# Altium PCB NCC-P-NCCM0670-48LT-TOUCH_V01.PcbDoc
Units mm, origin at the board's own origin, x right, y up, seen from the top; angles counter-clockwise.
Board outline 105 x 62 mm, 2 copper layers (Top Layer, Bottom Layer); 70 components, 72 nets, 253 pads, 227 vias.
Unrouted connection lines stored in the file: 181.
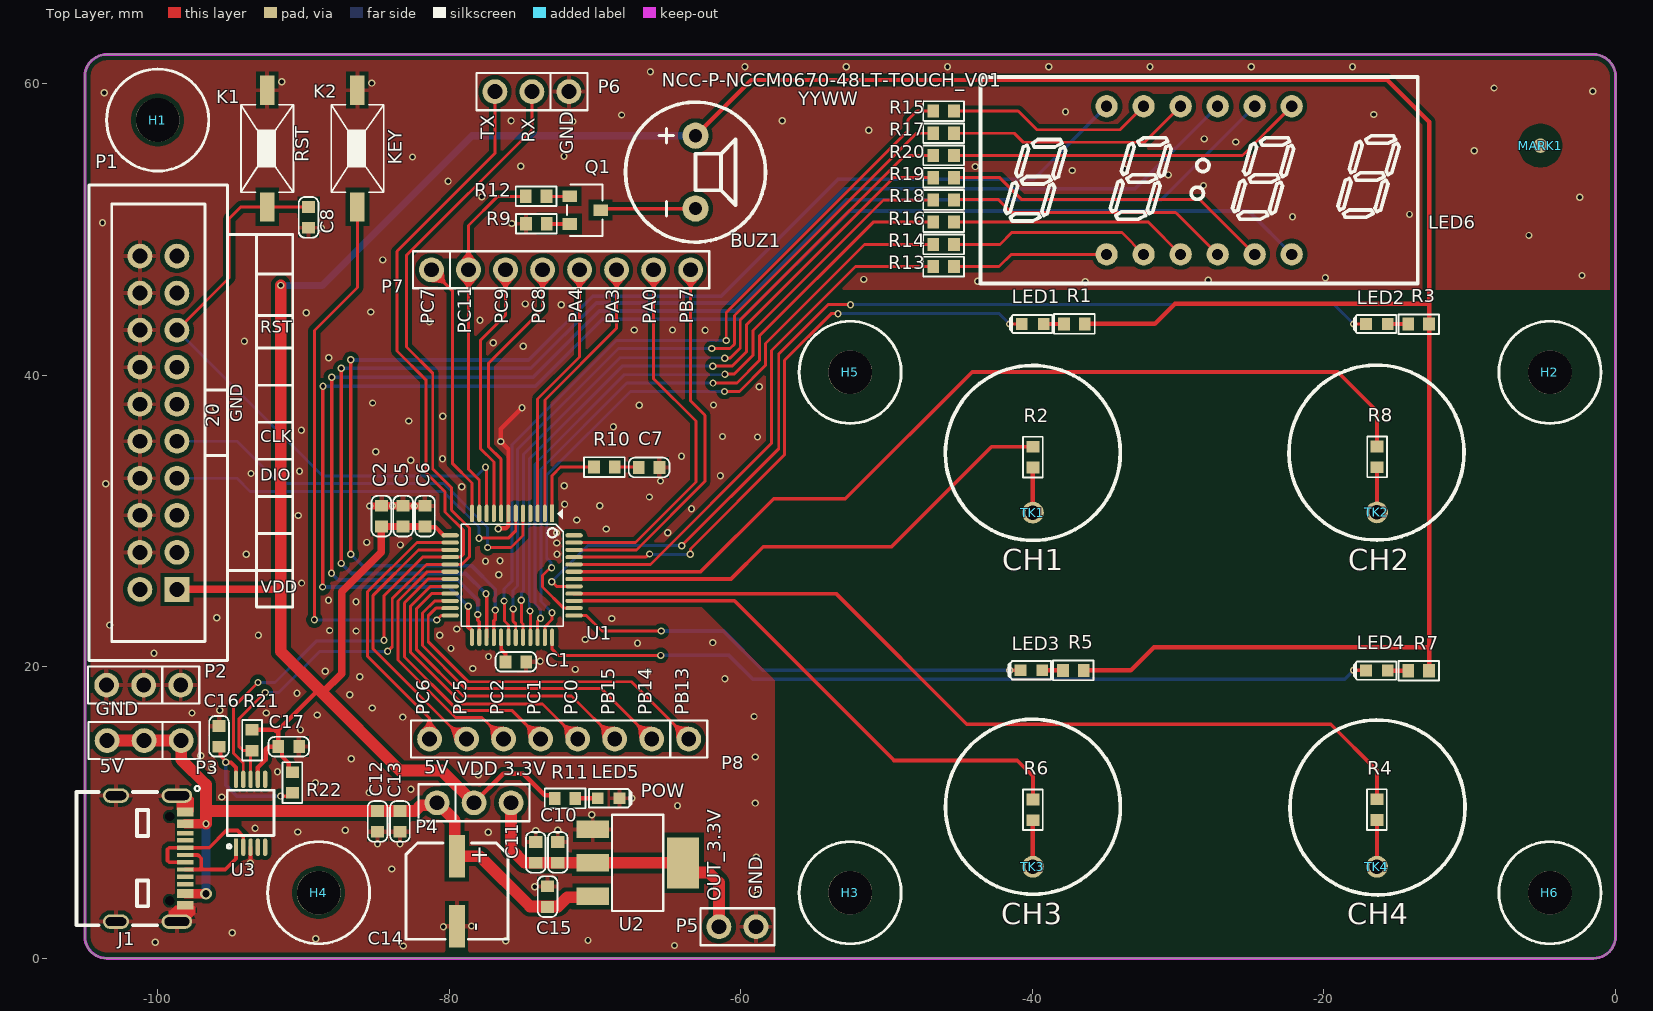
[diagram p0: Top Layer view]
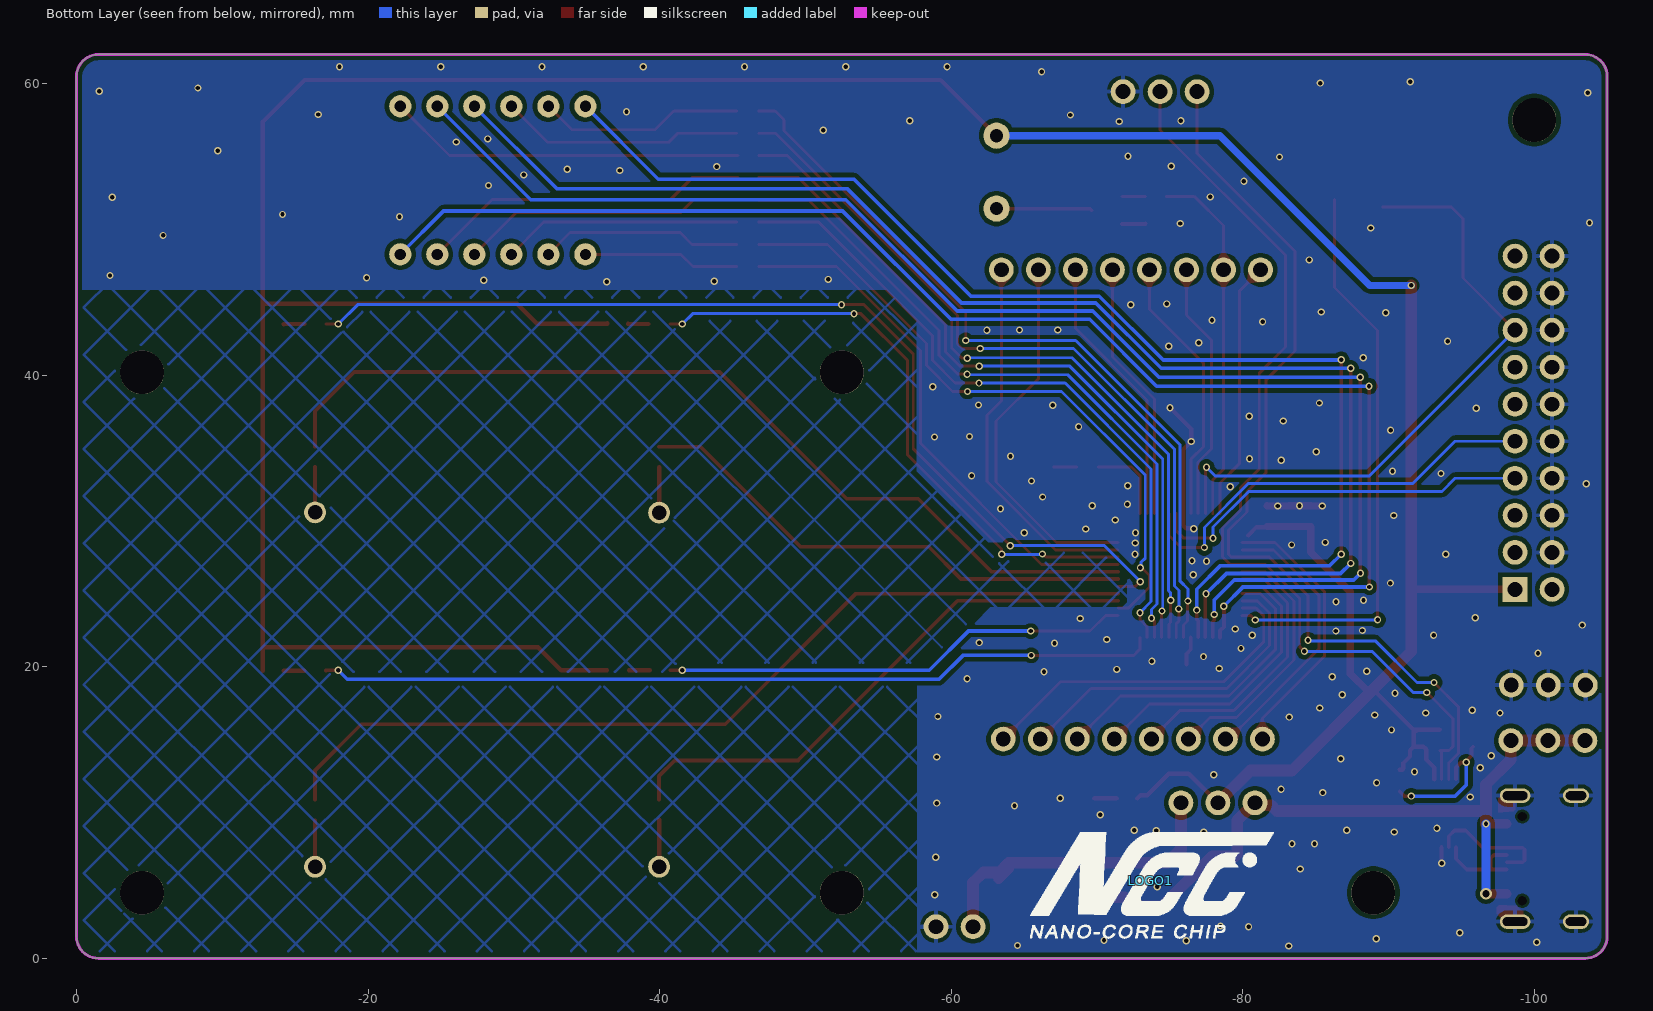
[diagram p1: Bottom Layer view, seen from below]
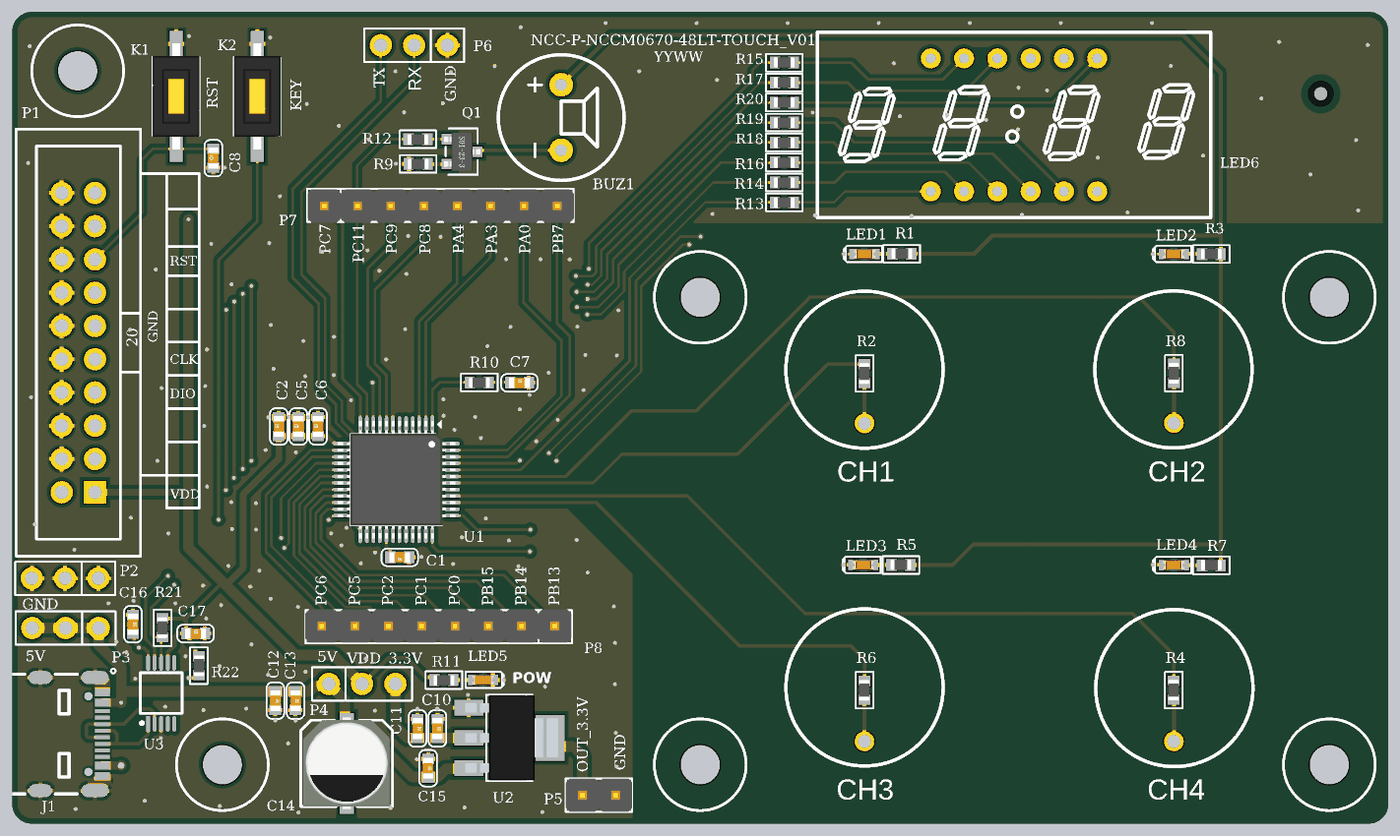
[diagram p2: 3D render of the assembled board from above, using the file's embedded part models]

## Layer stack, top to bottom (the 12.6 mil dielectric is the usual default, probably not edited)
Top Solder: solder mask 0.0102, Solder Resist, Dk 3.5
Top Layer: signal copper 0.0356
Dielectric 1: dielectric 0.32, FR-4, Dk 4.8
Bottom Layer: signal copper 0.0356
Bottom Solder: solder mask 0.0102, Solder Resist, Dk 3.5

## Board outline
-105,1.5 ccw(c-103.5,1.5) -103.5,0 -1.5,0 ccw(c-1.5,1.5) 0,1.5 0,60.5 ccw(c-1.5,60.5) -1.5,62 -103.5,62 ccw(c-103.5,60.5) -105,60.5

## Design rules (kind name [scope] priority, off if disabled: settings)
Clearance Clearance_2 [InComponent('J1')] p1: gap=0.15 ignorepadtopadclearanceinfootprint=FALSE
Clearance Clearance_1 [IsVia vs IsVia] p2: gap=0.3 ignorepadtopadclearanceinfootprint=FALSE
Clearance touch [InNet('KEY0') or InNet('KEY1') or InNet('KEY2') or InNet('KEY3') or InNet('KEY4') or InNet('KEY5') or InNet('NetKEY0_1') or InNet('NetKEY1_1') or InNet('NetKEY2_1') or InNet('NetKEY3_1') or InNet('NetKEY4_1') or InNet('NetKEY5_1') vs InPolygon] p3: gap=0.762 ignorepadtopadclearanceinfootprint=FALSE
Clearance polygon [InPolygon] p4: gap=0.3 ignorepadtopadclearanceinfootprint=FALSE
Clearance keepout [OnLayer('Keep-Out Layer')] p5: gap=0.35 ignorepadtopadclearanceinfootprint=FALSE
Clearance [All] p6: gap=0.2 ignorepadtopadclearanceinfootprint=FALSE
ComponentClearance [All] p1: gap=0 collisioncheckmode=3 verticalgap=0 showdistances=FALSE
HoleToHoleClearance [All] p1: gap=0 allowstackedmicrovias=TRUE
MinimumSolderMaskSliver [All] p1: minsoldermaskwidth=0
PolygonConnect isvia [isvia] p1: connectstyle=Direct reliefconductorwidth=0.254 reliefentries=4 polygonreliefangle="90 Angle" airgapwidth=0.254
PolygonConnect [All] p2: connectstyle=Relief reliefconductorwidth=0.3 reliefentries=4 polygonreliefangle="90 Angle" airgapwidth=0.25
RoutingVias [All] p1: holewidth=0.3 width=0.5 viastyle="Through Hole" minholewidth=0.25 minwidth=0.45 maxholewidth=0.5 maxwidth=0.8
SilkToSilkClearance [All] p1: silktosilkclearance=0
SilkToSolderMaskClearance [IsPad] p1: minsilkscreentomaskgap=0 clearancetoexposedcopper=TRUE
SolderMaskExpansion [All] p1: expansion=0.102 istentingtop=FALSE
Width [All] p1: maxlimit=5 minlimit=0.2 preferedwidth=0.3
25 further rules are at their usual default settings.

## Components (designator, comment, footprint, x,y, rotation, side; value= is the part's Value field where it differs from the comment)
BUZ1 "BUZZER-SMD/DIP-2P" BUZZER-D9P5-2P -63.11,53.93 r270 top
C1 "4.7nF" 0603C_0.6D -75.43,20.34 r180 top
C2 "10uF" 0603C_0.6D -84.657,30.334 r90 top
C5 "1uF" 0603C_0.6D -83.167,30.334 r90 top
C6 "0.1uF" 0603C_0.6D -81.667,30.334 r90 top
C7 "10pF" 0603C_0.6D -66.294,33.673 r0 top
C8 "0.1uF" 0603C_0.6D -89.65,50.828 r90 top
C10 "0.1uF" 0603C_0.6D -72.556,7.269 r270 top
C11 "10uF" 0603C_0.6D -74.066,7.269 r270 top
C12 "0.1uF" 0603C_0.6D -84.92,9.39 r270 top
C13 "10uF" 0603C_0.6D -83.38,9.39 r270 top
C14 "47uF" CS-L6.6W6.6 -79.48,4.61 r90 top
C15 "10uF" 0603C_0.6D -73.26,4.232 r270 top
C16 "0.1uF" 0603C_0.6D -95.79,15.23 r270 top
C17 "0.1uF" 0603C_0.6D -91.01,14.52 r0 top
H1 "HOLE" Toolinghole-3 -100,57.5 r0 top
H2 "HOLE" Toolinghole-3 -4.5,40.2 r0 top
H3 "HOLE" Toolinghole-3 -52.5,4.5 r180 top
H4 "HOLE" Toolinghole-3 -88.96,4.5 r0 top
H5 "HOLE" Toolinghole-3 -52.5,40.2 r0 top
H6 "HOLE" Toolinghole-3 -4.5,4.5 r180 top
J1 "TYPE-C_12P" TYPE-C-12 -100.49,6.84 r270 top locked
K1 "BUTTON-2" SW-6X3X2.5-2P-S -92.49,55.55 r90 top
K2 "BUTTON-2" SW-6X3X2.5-2P-S -86.3,55.55 r90 top
LED1 "DIODE-LED" D0603 -39.97,43.51 r0 top
LED2 "DIODE-LED" D0603 -16.37,43.51 r0 top locked
LED3 "DIODE-LED" D0603 -40.062,19.763 r0 top
LED4 "DIODE-LED" D0603 -16.37,19.74 r0 top locked
LED5 "DIODE-LED" D0603 -69.07,10.98 r180 top
LED6 "FJ3462AH" LED-SEG-TH_12P-L30.0-W14.0-P2.54-S10.16-BL_FJ3462XH -28.56,53.37 r0 top locked
LOGO1 "LOGO" LOGO-NCC -73.68,5.32 r180 bottom
MARK1 "MARK" MARK-Single -5.15,55.75 r0 top
P1 "HDR 20-D-M" "DC3 2.54_20" -99.95,36.74 r90 top locked
P2 "HDR 3-M" "SIP 2.54_3_S" -98.42,18.74 r270 top
P3 "HDR 3-M" "SIP 2.54_3_S" -98.39,14.94 r270 top
P4 "HDR 3-M" "SIP 2.54_3_S" -80.84,10.67 r90 top
P5 "HDR 2-M" "SIP 2.54_2_S" -61.5,2.17 r90 top
P6 "HDR 3-M" "SIP 2.54_3_S" -71.79,59.45 r270 top
P7 "HDR 8-M" "SIP 2.54_8_S" -81.22,47.23 r90 top
P8 "HDR 8-M" "SIP 2.54_8_S" -63.57,15.04 r270 top
Q1 "NPN" SOT-23-3A -70.671,51.323 r180 top
R1 "510R" 0603R_0.6D -37.12,43.52 r180 top
R2 "510R" 0603R_0.6D -39.96,34.379 r270 top
R3 "510R" 0603R_0.6D -13.5,43.5 r180 top
R4 "510R" 0603R_0.6D -16.371,10.2 r270 top
R5 "510R" 0603R_0.6D -37.192,19.753 r180 top
R6 "510R" 0603R_0.6D -39.961,10.188 r270 top
R7 "510R" 0603R_0.6D -13.5,19.73 r180 top
R8 "510R" 0603R_0.6D -16.36,34.4 r270 top
R9 "330R" 0603R_0.6D -74.021,50.393 r0 top
R10 "510R" 0603R_0.6D -69.354,33.703 r0 top
R11 "2K" 0603R_0.6D -72.058,10.967 r0 top
R12 "1K" 0603R_0.6D -74.042,52.273 r0 top
R13 "100R" 0603R_0.6D -46.09,47.449 r0 top
R14 "100R" 0603R_0.6D -46.09,48.974 r0 top
R15 "100R" 0603R_0.6D -46.09,58.123 r180 top
R16 "100R" 0603R_0.6D -46.09,50.499 r0 top
R17 "100R" 0603R_0.6D -46.09,56.598 r180 top
R18 "100R" 0603R_0.6D -46.09,52.024 r0 top
R19 "100R" 0603R_0.6D -46.09,53.548 r0 top
R20 "100R" 0603R_0.6D -46.09,55.073 r180 top
R21 "2K" 0603R_0.6D -93.52,14.962 r270 top
R22 "0R" 0603R_0.6D -90.76,12.06 r90 top
TK1 "HDR 1-M" TOUCH_PAD_1.5/1.0 -39.964,30.57 r180 top locked
TK2 "HDR 1-M" TOUCH_PAD_1.5/1.0 -16.364,30.591 r180 top locked
TK3 "HDR 1-M" TOUCH_PAD_1.5/1.0 -39.964,6.281 r180 top locked
TK4 "HDR 1-M" TOUCH_PAD_1.5/1.0 -16.364,6.281 r180 top locked
U1 "ATM0F3170C-LA7_simple" LQFP48(0.5)-7X7 -75.69,26.27 r270 top locked
U2 "AMS1117-3.3V" SOT-223-4 -67.056,6.549 r180 top
U3 "CH340E" MSOP10(0.5)-3x3 -93.63,9.95 r90 top

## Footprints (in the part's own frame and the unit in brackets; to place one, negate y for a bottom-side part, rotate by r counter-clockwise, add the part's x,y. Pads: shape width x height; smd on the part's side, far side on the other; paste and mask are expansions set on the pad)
0603C_0.6D [mm]
  rect 0.8x0.9 smd mask+0.076: 1(-0.712,0) 2(0.712,0)
  silkscreen extent -1.4,-0.68 1.4,0.67, body extent -0.8,-0.4 0.8,0.4, height 0.3
0603R_0.6D [mm]
  rect 0.8x0.9 smd: 1(-0.712,0) 2(0.712,0)
  silkscreen extent -1.4,-0.67 1.4,0.67, body extent -0.8,-0.42 0.8,0.38, height 0.38
BUZZER-D9P5-2P [mm]
  round 1.8 hole 0.9: 1(-2.5,0) 2(2.5,0)
  silkscreen extent -4.8,-4.8 4.8,4.8
CS-L6.6W6.6 [mm]
  rect 2.9x1.1 smd: 1(2.4,0) 2(-2.4,0)
  silkscreen extent -3.3,-3.5 3.3,3.5, body extent -3.5,-3.3 3.5,3.3, height 5.41
D0603 [mm]
  rect 0.8x0.8 smd: A(0.75,0) K(-0.75,0)
  silkscreen extent -1.59,-0.63 1.33,0.63, body extent -0.81,-0.4 0.81,0.4, height 0.6
"DC3 2.54_20" [mm]
  rect 1.7x1.7 hole 1.02: 1(-11.43,-1.27)
  round 1.7 hole 1.02: 2(-11.43,1.27) 3(-8.89,-1.27) 4(-8.89,1.27) 5(-6.35,-1.27) 6(-6.35,1.27) 7(-3.81,-1.27) 8(-3.81,1.27) 9(-1.27,-1.27) 10(-1.27,1.27) 11(1.27,-1.27) 12(1.27,1.27) 13(3.81,-1.27) 14(3.81,1.27) 15(6.35,-1.27) 16(6.35,1.27) 17(8.89,-1.27) 18(8.89,1.27) 19(11.43,-1.27) 20(11.43,1.27)
  silkscreen extent -16.31,-4.75 16.31,4.75
LED-SEG-TH_12P-L30.0-W14.0-P2.54-S10.16-BL_FJ3462XH [mil]
  round 60 hole 30: 1(-250,-200) 2(-150,-200) 3(-50,-200) 4(50,-200) 5(150,-200) 6(250,-200) 7(250,200) 8(150,200) 9(50,200) 10(-50,200) 11(-150,200) 12(-250,200)
  silkscreen extent -591,-279 591,279
LOGO-NCC [mm]
  silkscreen extent -8.25,-3.96 8.46,3.3
LQFP48(0.5)-7X7 [mm]
  rect 1.2x0.28 smd mask+0.051: 1(-4.25,2.75)
  oval 1.2x0.28 smd mask+0.051: 2(-4.25,2.25) 3(-4.25,1.75) 4(-4.25,1.25) 5(-4.25,0.75) 6(-4.25,0.25) 7(-4.25,-0.25) 8(-4.25,-0.75) 9(-4.25,-1.25) 10(-4.25,-1.75) 11(-4.25,-2.25) 12(-4.25,-2.75) 25(4.25,-2.75) 26(4.25,-2.25) 27(4.25,-1.75) 28(4.25,-1.25) 29(4.25,-0.75) 30(4.25,-0.25) 31(4.25,0.25) 32(4.25,0.75) 33(4.25,1.25) 34(4.25,1.75) 35(4.25,2.25) 36(4.25,2.75)
  oval 0.28x1.2 smd mask+0.051: 13(-2.75,-4.25) 14(-2.25,-4.25) 15(-1.75,-4.25) 16(-1.25,-4.25) 17(-0.75,-4.25) 18(-0.25,-4.25) 19(0.25,-4.25) 20(0.75,-4.25) 21(1.25,-4.25) 22(1.75,-4.25) 23(2.25,-4.25) 24(2.75,-4.25) 37(2.75,4.25) 38(2.25,4.25) 39(1.75,4.25) 40(1.25,4.25) 41(0.75,4.25) 42(0.25,4.25) 43(-0.25,4.25) 44(-0.75,4.25) 45(-1.25,4.25) 46(-1.75,4.25) 47(-2.25,4.25) 48(-2.75,4.25)
  round 0.3 on Mech15 mask+0.3: ""(-4.25,2.75)
  silkscreen extent -4.58,-3.5 3.5,3.5, body extent -4.5,-4.49 4.5,4.51, height 1.56
MARK-Single [mm]
  round 1 smd mask+0.5: 1(0,0)
  Top Layer pour cut-out: -1.5,0 -1.386,-0.574 -1.061,-1.061 -0.574,-1.386 0,-1.5 0,-1.5 0.574,-1.386 1.061,-1.061 1.386,-0.574 1.5,0 1.5,0 1.386,0.574 1.061,1.061 0.574,1.386 0,1.5 0,1.5 -0.574,1.386 -1.061,1.061 -1.386,0.574 -1.5,0
MSOP10(0.5)-3x3 [mm]
  rect 1.2x0.3 smd mask+0.05: 1(-2.325,1)
  oval 1.2x0.3 smd mask+0.05: 2(-2.325,0.5) 3(-2.325,0) 4(-2.325,-0.5) 5(-2.325,-1) 6(2.325,-1) 7(2.325,-0.5) 8(2.325,0) 9(2.325,0.5) 10(2.325,1)
  rect 0.5x0.25 on Mech1 mask+0.051: ""(-2.25,-1) ""(-2.25,-0.5) ""(-2.25,0) ""(-2.25,0.5) ""(-2.25,1)
  silkscreen extent -2.4,-1.6 1.58,1.6, body extent -1.5,-1.5 1.5,1.5, height 1.09
"SIP 2.54_2_S" [mm]
  round 1.7 hole 1.02: 1(0,0) 2(0,-2.54)
  silkscreen extent -1.27,-3.81 1.27,1.27, body extent -1.27,-3.81 1.27,1.27, height 10.3
"SIP 2.54_3_S" [mm]
  round 1.7 hole 1.02: 1(0,0) 2(0,-2.54) 3(0,-5.08)
  silkscreen extent -1.27,-6.35 1.27,1.27
"SIP 2.54_8_S" [mm]
  round 1.7 hole 1.02: 1(0,0) 2(0,-2.54) 3(0,-5.08) 4(0,-7.62) 5(0,-10.16) 6(0,-12.7) 7(0,-15.24) 8(0,-17.78)
  silkscreen extent -1.27,-19.05 1.27,1.27, body extent -1.32,-19.08 1.22,1.24, height 0.7
SOT-23-3A [mm]
  rect 1x0.8 smd: B(1.05,-0.95) C(-1.05,0) E(1.05,0.95)
  rect 0.55x0.5 on Mech1: ""(-1.025,0) ""(1.025,0.95) ""(1.025,-0.95)
  silkscreen extent -1.19,-1.77 1.25,1.77, body extent -1.41,-1.45 1.41,1.45, height 1.22
SOT-223-4 [mm]
  rect 2.2x1.2 smd: 1(3.1,-2.3) 2(3.1,0) 3(3.1,2.3)
  rect 2.2x3.5 smd: 2(-3.1,0)
  silkscreen extent -1.74,-3.3 1.77,3.3, body extent -3.72,-3.25 3.37,3.25, height 1.65
SW-6X3X2.5-2P-S [mm]
  rect 2x1 smd: 1(-4,0) 2(4,0)
  silkscreen extent -3,-1.8 3,1.8, body extent -4.07,-1.8 4.07,1.8, height 2.39
Toolinghole-3 [mm]
  round 3 hole 3 unplated: 1(0,0)
  silkscreen extent -3.5,-3.5 3.5,3.5
TOUCH_PAD_1.5/1.0 [mm]
  round 1.5 hole 1: 1(0,0)
TYPE-C-12 [mm]
  round 0 hole 0.65 unplated paste+0 mask+0.05: 0(-2.89,1.307) 0(2.89,1.307)
  oval 1x2.1 hole 0.6 slot 1.7 at 90 deg paste+0 mask+0.05: 1(-4.32,1.808) 4(4.32,1.808)
  oval 1x1.8 hole 0.6 slot 1.4 at 90 deg paste+0 mask+0.05: 2(-4.32,-2.372) 3(4.32,-2.372)
  rect 0.6x1.15 smd paste-100 mask+0.05: A1-B12(-3.2,2.372) A4-B9(-2.4,2.372) B1-A12(3.2,2.372) B4-A9(2.4,2.372)
  rect 0.3x1.15 smd paste-100 mask+0.05: A5(-1.25,2.372) A6(-0.25,2.372) A7(0.25,2.372) A8(1.25,2.372) B5(1.75,2.372) B6(0.75,2.372) B7(-0.75,2.372) B8(-1.75,2.372)
  silkscreen extent -4.98,-5.08 4.57,3.37

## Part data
BUZ1: "蜂鸣器"
C1 C2 C5 C6 C7 C8 C10 C11 C12 C13 C15 C16 C17: library part CAP-NP
C14: library part CAP-P
H1 H2 H3 H4 H5 H6: "定位孔"
J1: "C136423"
K1 K2: "轻触开关"
LED1 LED2 LED3 LED4: "白灯"
LED5: "红灯"
LED6: BOM_Manufacturer="Shenzhen Zhihao Elec"
P1 P2 P3 P4 P5 P6 P7 P8: "公头"
R1 R2 R3 R4 R5 R6 R7 R8 R9 R10 R11 R12 R13 R14 R15 R16 R17 R18 R19 R20 R21 R22: library part RES
TK1 TK2 TK3 TK4: "C3015094"
U2: library part AMS1117

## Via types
v1: diameter 0.5, hole 0.3, Top Layer to Bottom Layer, tented both sides, 226 vias
v2: diameter 0.8, hole 0.5, Top Layer to Bottom Layer, tented both sides, 1 vias

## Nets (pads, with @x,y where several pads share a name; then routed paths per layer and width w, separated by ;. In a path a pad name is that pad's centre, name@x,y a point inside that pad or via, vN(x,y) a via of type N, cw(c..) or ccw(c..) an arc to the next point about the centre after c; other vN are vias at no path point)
BUZ: P7.2 R12.1 U1.11 | length 24.8
  Top Layer w0.2: U1.11 -77.94,32.81 -78.68,33.55 -78.68,46.53 -78.68,50.26 -76.667,52.273 R12.1
CH1: R2.1 U1.42 | length 35.2
  Top Layer w0.25: U1.42 -60.67,26.02 -58.46,28.23 -49.66,28.23 -42.799,35.091 R2.1
CH2: R8.1 U1.43 | length 64.3
  Top Layer w0.25: U1.43@-71.44,26.51 -62.76,26.51 -57.75,31.52 -52.83,31.52 -44.13,40.22 -19.05,40.22 -16.36,37.53 R8.1
CH3: R6.1 U1.39 | length 38.1
  Top Layer w0.25: U1.39 -60.44,24.52 -49.5,13.58 ; -49.5,13.57 -41.03,13.57 -39.961,12.501 R6.1
CH4: R4.1 U1.40 | length 62.1
  Top Layer w0.25: U1.40 -53.47,25.02 -44.51,16.06 -19.54,16.06 -16.361,12.881 R4.1@-16.361,10.882
COM1: LED6.12 U1.28 | length 86.7
  Top Layer w0.25: v1(-86.75,27.72) v1(-86.75,41.07) ; U1.28 -76.94,23.14 -76.84,23.24 v1(-76.84,23.89)
  Bottom Layer w0.25: v1(-86.75,27.72) -85.97,26.94 -78.47,26.94 -76.84,25.31 v1(-76.84,23.89) ; v1(-86.75,41.07) -86.72,41.04 -74.539,41.04 -70.159,45.42 -61.36,45.42 -53.33,53.45 -39.91,53.45 LED6.12
COM2: LED6.9 U1.27 | length 94.7
  Top Layer w0.2: v1(-77.48,25) v1@-77.44,24.96
  Top Layer w0.25: v1(-87.4,27.09) v1(-87.4,40.47) ; U1.27 v1@-77.44,24.96
  Bottom Layer w0.25: v1(-87.4,27.09) -86.71,26.4 -78.88,26.4 v1(-77.48,25) ; v1(-87.4,40.47) -74.401,40.47 -69.921,44.95 -60.71,44.95 -52.86,52.8 -32.94,52.8 LED6.9
COM3: LED6.8 U1.26 | length 97.9
  Top Layer w0.25: v1(-88.08,26.41) -88.07,26.42 -88.07,39.86 v1(-88.06,39.87) ; v1(-78.05,23.59) -78.05,23.19 -77.94,23.08 U1.26
  Bottom Layer w0.25: v1(-88.08,26.41) -87.62,25.95 -79.42,25.95 -78.05,24.58 v1(-78.05,23.59) ; v1(-88.06,39.87) -74.238,39.87 -69.708,44.4 -60.41,44.4 -52.77,52.04 -31.16,52.04 LED6.8
COM4: LED6.6 U1.25 | length 99.2
  Top Layer w0.25: v1(-88.69,25.47) -88.675,25.485 -88.675,39.225 v1(-88.66,39.24)
  Top Layer w0.27: v1(-78.7,24.16) -78.7,22.743 -78.44,22.483 U1.25 -78.442,22.018 U1.25@-78.442,22.02
  Bottom Layer w0.25: v1(-88.69,25.47) -80.01,25.47 v1(-78.7,24.16) ; v1(-88.66,39.24) -74.09,39.24 -69.5,43.83 -59.98,43.83 -52.55,51.26 -25.18,51.26 LED6.6
D+: J1.A6 J1.B6 U3.1 | length 6.8
  Top Layer w0.25: J1.B6 -97.17,6.09 ; J1.A6 -97.241,7.09 -97.02,6.869 -97.02,6.24 ; U3.1 -94.63,6.83 -95.37,6.09 -96.87,6.09 ; -97.17,6.09 -96.87,6.09 ; -97.17,6.09 -97.02,6.24 ; -97.02,6.24 -96.87,6.09
D-: J1.A7 J1.B7 U3.2 | length 8.7
  Top Layer w0.25: J1.A7 -99.213,6.59 -99.33,6.707 -99.33,7.473 -99.213,7.59 J1.B7 -96.47,7.59 -95.29,8.77 -94.52,8.77 -94.13,8.38 U3.2
GND: C1.1 C2.2 C5.2 C6.2 C7.2 C8.1 C10.1 C11.1 C12.2 C13.2 C14.2 C15.1 C16.1 C17.2 J1.1 J1.2 J1.3 J1.4 J1.A1-B12 J1.B1-A12 K1.2 K2.2 LED5.K P1.4 P1.6 P1.8 P1.10 P1.12 P1.14 P1.16 P1.18 P1.20 P2.1 P2.2 P2.3 P5.2 P6.1 R9.1 U1.7 U2.1 U3.3 | length 14.6
  Top Layer w0.3: v1(-93.65,6.53) -93.63,6.55 U3.3 ; v1(-76.63,29.46) -76.592,29.498 -76.116,29.498 -75.94,29.674 -75.94,34.92 v1(-76.47,35.45) -76.47,36.31 v1(-75.01,37.77)
  Top Layer w0.5: v1(-85.46,31.03) -84.673,31.03 C2.2 -84.651,31.04 v1(-83.89,31.04) -83.173,31.04 C5.2 -83.151,31.03 -81.683,31.03 C6.2
  other v1: -83.16,0.85 -64.55,0.88 -100.16,1.11 -76.13,1.2 -70.48,1.23 -89.16,1.34 -94.89,1.75 -80.4,2.17 -78.47,2.22 -58.88,4.36 -74.14,4.92 -83.94,6.13 -58.94,6.93 -84.92,7.87 -83.38,7.86 -77.33,8.64 -90.39,8.67 -87.14,8.78 -74.07,8.77 -72.56,8.79 -93.32,8.93 -70.22,9.84 -64.34,10.46 -59.01,10.65 -67.483,10.98 -95.6,11.07 -85.48,11.37 -82.63,11.6 -89.18,12.04 -78.02,12.59 -91.78,12.79 -96.29,13.08 -86.73,13.69 -59.01,13.81 -97.05,13.89 -90.2,15.67 -83.19,16.55 -59.09,16.59 -89.05,16.69 -97.65,16.83 -92.56,16.83 -95.74,17.01 -85.28,17.17 -86.83,18.09 -90.44,18.19 -61.09,19.18 -86.13,19.32 -66.37,19.66 -88.51,19.69 -71.35,19.82 -78.39,19.88 -73.77,20.38 -77.31,20.7 -100.25,20.92 -79.88,21.26 -67.09,21.62 -61.92,21.66 -70.68,21.87 -93.09,22.17 -80.65,22.17 -86.39,22.45 -88.21,22.49 -79.49,22.59 -103.28,22.86 -68.86,23.31 -95.95,23.37 -86.397,24.47 -88.28,24.56 -90.13,25.74 -76.61,26.32 -77.51,27.23 -76.52,27.28 -93.92,27.71 -72.61,27.72 -83.35,28.36 -72.63,28.49 -85.66,28.53 -72.64,29.19 -65.01,29.2 -69.23,29.45 -71.25,30.07 -90.35,30.38 -63.38,30.84 -82.41,31.03 -69.67,31.05 -72.09,31.15 -66.27,31.65 -79.14,32.34 -72.11,32.42 -103.56,32.56 -65.51,32.74 -61.4,33.11 -93.6,33.26 -90.27,33.42 -82.64,34.17 -80.46,34.26 -64.07,34.44 -85.05,34.74 -58.86,35.76 -61.26,35.8 -90.14,36.22 -68.74,36.47 -82.78,36.86 -80.45,37.19 -96.01,37.73 -66.97,37.94 -61.87,37.96 -85.26,38.09 -58.74,39.2 -88.27,41.2 -74.92,41.99 -76.99,42.23 -94.05,42.32 -67.31,43.1 -64.69,43.1 -62.45,43.09 -81.36,43.67 -77.89,43.78 -89.81,44.28 -85.38,44.34 -72.31,44.83 -74.78,44.89 -36.38,46.42 -43.75,46.45 -27.945,46.51 -51.57,46.57 -19.9,46.69 -2.3,46.84 -84.57,47.91 -5.94,49.59 -88.79,50.1 -75.72,50.41 -103.79,50.46 -22.16,50.87 -14.13,51.03 -2.46,52.2 -77.78,52.23 -28.26,53.01 -80.08,53.3 -30.68,53.74 -37.27,54.04 -33.67,54.13 -43.92,54.31 -75.1,54.33 -82.52,54.97 -72.13,55.02 -9.69,55.39 -26.04,56 -28.21,56.21 -51.22,56.8 -71.52,57.4 -75.76,57.46 -57.16,57.46 -68.18,57.85 -16.59,57.88 -37.73,58.08 -103.67,59.38 -1.57,59.47 -8.33,59.7 -85.31,60.04 -91.5,60.14 -66.2,60.82 -59.72,61.15 -52.773,61.15 -45.827,61.15 -38.88,61.15 -31.933,61.15 -24.987,61.15 -18.04,61.15
KEY: K2.1 U1.24 | length 39.5
  Top Layer w0.2: v1(-89.25,23.22) -89.25,43.06 -86.3,46.01 K2.1 K2.1@-86.3,52.05 ; v1(-80.85,23.21) -80.85,23.214 -80.559,23.505 -79.955,23.505 U1.24
  Bottom Layer w0.2: v1@-89.25,23.21 v1(-80.85,23.21)
LED1: LED1.K U1.45 | length 42
  Top Layer w0.2: U1.45 -66.526,27.52 -66.307,27.739 v1(-66.259,27.739) ; v1(-63.47,27.71) -63.461,27.719 -63.461,28.079 -57,34.54 -57,41.02 -53.8,44.22 v1(-53.33,44.22) ; v1(-41.557,43.51) LED1.K
  Bottom Layer w0.2: v1(-66.259,27.739) -66.23,27.71 v1(-63.47,27.71) ; v1(-53.33,44.22) -42.267,44.22 v1(-41.557,43.51)
LED2: LED2.K U1.41 | length 69.8
  Top Layer w0.2: v1@-72.969,25.84 -72.649,25.52 U1.41 ; v1(-64.05,28.31) -57.4,34.96 -57.4,41.46 -54.02,44.84 v1(-52.48,44.84) ; v1(-17.957,43.51) LED2.K
  Bottom Layer w0.2: v1(-72.97,25.84) -70.5,28.31 v1(-64.05,28.31) v1@-63.98,28.31 ; v1(-52.48,44.84) -19.287,44.84 v1(-17.957,43.51)
LED3: LED3.K U1.37 | length 32.3
  Top Layer w0.2: U1.37 -70.6,23.52 -69.53,22.45 v1(-65.46,22.45)
  Top Layer w0.25: v1(-41.561,19.763) LED3.K@-40.724,19.763
  Bottom Layer w0.25: v1(-65.46,22.45) -61.19,22.45 -58.503,19.763 v1(-41.561,19.763)
LED4: LED4.K U1.36 | length 57.8
  Top Layer w0.2: U1.36 -72.94,21.2 -72.52,20.78 v1(-65.5,20.78)
  Top Layer w0.25: v1(-17.957,19.763) -17.143,19.763 LED4.K
  Bottom Layer w0.25: v1(-65.5,20.78) -60.81,20.78 -59.168,19.138 -18.582,19.138 v1(-17.957,19.763)
NetBUZ1_2: BUZ1.2 Q1.C | length 6.6
  Top Layer w0.25: Q1.C -69.514,51.43 BUZ1.2
NetC7_1: C7.1 R10.2 | length 1.6
  Top Layer w0.2: R10.2 C7.1@-67.036,33.703
NetC10_2: C10.2 C11.2 P4.3 P5.1 U2.2 | length 22.8
  Top Layer w0.8: P4.3 -75.76,7.47 -74.839,6.549 -70.156,6.549 U2.2@-63.956,6.549 ; U2.2@-63.256,5.515 -63.956,6.215 U2.2@-63.956,6.549 ; P5.1 -61.5,5.2 -62.19,5.89 -63.297,5.89 U2.2@-63.956,6.549
NetC16_2: C16.2 R22.1 U3.10 | length 9.5
  Top Layer w0.25: C16.2 -95.692,14.42 -95.692,13.89 -95.33,13.528 v1(-95.33,13.46) ; v1@-95.33,13.439 v1(-95.33,13.46) ; U3.10 -94.63,13.09 -94.973,13.433 -95.303,13.433 v1(-95.33,13.46) ; v1(-91.55,11.13) -91.085,11.13 -90.76,11.455 R22.1@-90.76,11.468
  Bottom Layer w0.25: v1(-95.33,13.46) -95.33,11.89 -94.56,11.12 -91.56,11.12 v1(-91.55,11.13)
NetLED1_A: LED1.A R1.2 | length 1.4
  Top Layer w0.3: LED1.A -37.842,43.51 R1.2
NetLED2_A: LED2.A R3.2 | length 1.4
  Top Layer w0.3: LED2.A -14.222,43.51 R3.2
NetLED3_A: LED3.A R5.2 | length 1.4
  Top Layer w0.3: LED3.A -37.914,19.763 R5.2
NetLED4_A: LED4.A R7.2 | length 1.4
  Top Layer w0.3: LED4.A -14.222,19.74 R7.2
NetLED5_A: LED5.A R11.2 | length 1.5
  Top Layer w0.3: R11.2 -71.333,10.98 LED5.A
NetLED6_1: LED6.1 R13.2 | length 10.7
  Top Layer w0.2: R13.2@-45.29,47.449 -42.291,47.449 -41.45,48.29 LED6.1
NetLED6_2: LED6.2 R14.2 | length 13.9
  Top Layer w0.2: R14.2@-45.29,48.974 -42.226,48.974 -41.42,49.78 -33.86,49.78 LED6.2
NetLED6_3: LED6.3 R16.2 | length 16.4
  Top Layer w0.2: R16.2@-45.29,50.499 -32.039,50.499 LED6.3
NetLED6_4: LED6.4 R18.2 | length 19.6
  Top Layer w0.2: R18.2@-45.29,52.04 -42.32,52.04 -41.45,51.17 -30.17,51.17 LED6.4
NetLED6_5: LED6.5 R19.2 | length 22.8
  Top Layer w0.2: R19.2 -42.238,53.548 -40.73,52.04 -28.5,52.04 LED6.5
NetLED6_7: LED6.7 R20.1 | length 24.6
  Top Layer w0.2: R20.1 -25.587,55.073 LED6.7
NetLED6_10: LED6.10 R17.1 | length 16.7
  Top Layer w0.2: R17.1@-45.29,56.598 -41.238,56.598 -40.62,55.98 -32.3,55.98 LED6.10
NetLED6_11: LED6.11 R15.1 | length 14.1
  Top Layer w0.2: R15.1@-45.29,58.123 -40.973,58.123 -39.69,56.84 -33.98,56.84 LED6.11
NetQ1_B: Q1.B R12.2 | length 1.6
  Top Layer w0.2: R12.2 Q1.B
NetQ1_E: Q1.E R9.2 | length 1.6
  Top Layer w0.3: R9.2 -73.289,50.373 Q1.E
NetR2_2: R2.2 TK1.1 | length 3.1
  Top Layer w0.3: TK1.1 R2.2@-39.964,33.688
NetR4_2: R4.2 TK4.1 | length 3.2
  Top Layer w0.3: TK4.1 R4.2@-16.364,9.458
NetR6_2: R6.2 TK3.1 | length 3.2
  Top Layer w0.3: TK3.1 R6.2@-39.964,9.507
NetR8_2: R8.2 TK2.1 | length 3.1
  Top Layer w0.3: TK2.1 R8.2@-16.364,33.7
NetR10_1: R10.1 U1.1 | length 5.7
  Top Layer w0.2: U1.1 -72.94,33.125 -72.363,33.703 R10.1
NRST: C8.2 K1.1 P1.15 U1.10 | length 43.7
  Top Layer w0.2: P1.15 -95.1,46.67 -95.1,50.73 -94.28,51.55 C8.2@-89.59,51.55 ; v1(-77.51,33.68) -77.455,33.625 -77.455,30.535 U1.10
  Bottom Layer w0.2: P1.15 -88.69,33.1 -78.09,33.1 v1(-77.51,33.68)
PA0: P7.7 U1.47 | length 25.8
  Top Layer w0.2: U1.47 -67.226,28.52 -63.08,32.666 -63.08,36.86 -65.98,39.76 P7.7
PA3: P7.6 U1.2 | length 18.7
  Top Layer w0.2: U1.2 -73.44,32.041 -73.437,32.044 -73.437,38.303 -68.52,43.22 P7.6
PA4: P7.5 U1.3 | length 17.9
  Top Layer w0.2: U1.3 -73.94,38.366 -71.06,41.246 P7.5
PB7: P7.8 U1.46 | length 25.8
  Top Layer w0.2: U1.46 -67.16,28.02 -62.46,32.72 -62.46,37.25 -63.44,38.23 P7.8
PB13: P8.1 U1.23 | length 24.1
  Top Layer w0.2: U1.23 -80.92,24.02 -81.44,23.5 -81.44,21.71 -78.7,18.97 -67.5,18.97 P8.1
PB14: P8.2 U1.22 | length 22.9
  Top Layer w0.2: U1.22 -81,24.52 -81.84,23.68 -81.84,21.45 -78.9,18.51 -69.58,18.51 P8.2
PB15: P8.3 U1.21 | length 21.7
  Top Layer w0.2: U1.21 -81.2,25.02 -82.26,23.96 -82.26,21.204 -79.056,18 -71.61,18 P8.3
PC0: P8.4 U1.20 | length 20.4
  Top Layer w0.2: U1.20 -81.29,25.52 -82.67,24.14 -82.67,21.01 -79.11,17.45 -73.6,17.45 P8.4
PC1: P8.5 U1.19 | length 19.2
  Top Layer w0.2: U1.19 -81.439,26.02 -83.07,24.389 -83.07,20.68 -79.38,16.99 -75.68,16.99 P8.5
PC2: P8.6 U1.18 | length 17.9
  Top Layer w0.2: U1.18 -81.504,26.52 -83.51,24.514 -83.51,20.47 -79.57,16.53 -77.76,16.53 P8.6
PC5: P8.7 U1.15 | length 19.2
  Top Layer w0.2: U1.15 -82.1,28.02 -85.22,24.9 -85.22,21.21 -79.05,15.04 P8.7
PC6: P8.8 U1.14 | length 18.9
  Top Layer w0.2: P8.8 -81.35,16.47 -85.62,20.74 -85.62,25.12 -82.22,28.52 U1.14
PC7: P7.1 U1.12 | length 17.9
  Top Layer w0.2: P7.1 -79.79,45.8 -79.79,33.96 -78.44,32.61 U1.12
PC8: P7.4 U1.8 | length 18.6
  Top Layer w0.2: U1.8 -76.44,34.23 -77.32,35.11 -77.32,40.8 -73.6,44.52 P7.4
PC9: P7.3 U1.9 | length 17.8
  Top Layer w0.2: U1.9 -76.94,34.04 -77.87,34.97 -77.87,42.39 -76.14,44.12 P7.3
SEG2: R15.2 U1.30 | length 53.5
  Top Layer w0.2: v1@-76.21,24.51 -76.21,23.14 -75.94,22.87 U1.30 ; v1(-61,42.38) -61,44.3 -48.53,56.77 -48.53,57.52 -47.927,58.123 R15.2
  Bottom Layer w0.2: v1(-76.24,24.51) -76.24,25.33 -75.71,25.86 -75.71,35.21 -68.54,42.38 v1(-61,42.38)
SEG3: R17.2 U1.31 | length 51.7
  Top Layer w0.2: v1(-75.62,23.97) -75.62,23.127 -75.44,22.947 U1.31 ; v1(-61.99,41.83) -60.74,41.83 -60.44,42.13 -60.44,44.1 -47.942,56.598 R17.2
  Bottom Layer w0.2: v1(-75.62,23.97) -75.62,25.23 -75.31,25.54 -75.31,34.92 -68.4,41.83 v1(-61.99,41.83)
SEG4: R20.2 U1.32 | length 50.4
  Top Layer w0.2: v1(-75.06,24.57) -75.05,24.56 -75.05,23.037 -74.94,22.927 U1.32 ; v1(-61.1,41.17) -61.096,41.174 -60.726,41.174 -60.04,41.86 -60.04,43.79 -48.757,55.073 R20.2
  Bottom Layer w0.2: v1(-75.06,24.57) -75.05,24.58 -75.05,25.08 -74.91,25.22 -74.91,34.58 -68.29,41.2 v1@-61.098,41.2
SEG5: R19.1 U1.33 | length 49
  Top Layer w0.2: U1.33 v1@-74.44,23.83 ; v1(-61.93,40.62) -60.6,40.62 -59.6,41.62 -59.6,43.48 -49.532,53.548 R19.1
  Bottom Layer w0.2: v1(-74.46,23.83) -74.51,23.88 -74.51,34.25 -68.14,40.62 v1(-61.93,40.62)
SEG6: R18.1 U1.34 | length 47.9
  Top Layer w0.2: U1.34 -73.94,23.13 v1(-73.74,23.33) ; v1(-61.09,40.07) -60.46,40.07 -59.16,41.37 -59.16,43.07 -50.206,52.024 R18.1
  Bottom Layer w0.2: v1(-73.74,23.33) -73.74,23.927 -74.11,24.297 -74.11,33.91 -67.99,40.03 v1@-61.08,40.03
SEG7: R16.1 U1.35 | length 47
  Top Layer w0.2: U1.35 -73.44,22.75 -72.95,23.24 v1(-72.95,23.71) ; v1(-61.91,39.46) -60.27,39.46 -58.73,41 -58.73,42.69 -50.921,50.499 R16.1
  Bottom Layer w0.2: v1(-72.95,23.71) -73.71,24.47 -73.71,33.57 -67.82,39.46 v1(-61.91,39.46)
SEG8: R14.1 U1.38 | length 44.8
  Top Layer w0.2: v1(-72.98,26.8) -73.061,26.8 -73.6,26.261 -73.6,25.47 -72.15,24.02 U1.38 ; v1(-61.12,38.885) -60.095,38.885 -58.3,40.68 -58.3,42.18 -51.506,48.974 R14.1
  Bottom Layer w0.2: v1(-72.98,26.8) -73.009,26.829 -73.009,27.149 -73.31,27.45 -73.31,33.15 -67.575,38.885 v1(-61.12,38.885)
SEG14: R13.1 U1.44 | length 36.8
  Top Layer w0.2: U1.44 -66.2,27.02 -57.89,35.33 -57.89,41.69 -52.131,47.449 R13.1
SWCLK: P1.9 U1.5 | length 29.4
  Top Layer w0.2: v1(-77.37,28.18) -75.76,28.18 -74.94,29 U1.5
  Bottom Layer w0.2: P1.9 -94.56,35.47 -91.66,32.57 -80.38,32.57 -77.37,29.56 v1(-77.37,28.18)
SWDIO: P1.7 U1.6 | length 26.8
  Top Layer w0.2: v1(-77.96,28.82) -75.95,28.82 -75.44,29.33 U1.6
  Bottom Layer w0.2: P1.7 -94.56,32.93 -93.66,32.03 -80.406,32.03 -77.96,29.584 v1(-77.96,28.82)
TK_CTANK: C1.2 U1.29 | length 2
  Top Layer w0.25: U1.29 -76.44,21.18 -76.14,20.88 C1.2@-76.14,20.16
USART1_RX: P6.2 R21.2 U1.17 U3.8 | length 64.5
  Top Layer w0.2: U3.8 -93.63,14.14 R21.2 -93.523,14.253 -94.153,14.253 -94.41,14.51 -94.41,16.46 v1(-92.632,18.238) ; v1(-84.23,21.06) -83.91,21.38 -83.91,24.68 -81.57,27.02 U1.17 -79.14,27.02 -78.61,27.55 -78.61,29.51 -79.84,30.74 -79.84,32.28 -81.13,33.57 -81.13,40.14 -82.932,41.942 -82.932,48.228 -74.33,56.83 P6.2
  Bottom Layer w0.2: v1(-92.632,18.238) -91.692,18.238 -88.87,21.06 v1(-84.23,21.06)
USART1_TX: P6.3 U1.16 U3.9 | length 63.6
  Top Layer w0.2: U3.9 -94.13,13.4 -94.81,14.08 -94.81,17.23 v1(-93.119,18.921) ; v1(-84.48,21.82) -84.48,24.87 -81.83,27.52 U1.16 -79.23,27.52 -79.01,27.74 -79.01,29.34 -80.29,30.62 -80.29,32 -81.608,33.318 -81.608,39.688 -83.59,41.67 -83.59,48.5 -76.87,55.22 P6.3
  Bottom Layer w0.2: v1(-93.119,18.921) -91.949,18.921 -89.09,21.78 -84.52,21.78 v1(-84.48,21.82)
VDD: BUZ1.1 C2.1 C5.1 C6.1 C17.1 P1.1 P4.2 R1.1 R3.1 R5.1 R7.1 R11.1 R21.1 R22.2 U1.13 U3.7 | length 258.8
  Top Layer w0.3: R21.1 -91.965,15.674 ; U3.7 -93.13,13.091 -92.59,13.631 -92.59,14.335 -92.401,14.524 C17.1@-91.817,14.524 ; R22.2@-90.76,12.942 -90.939,12.942 -91.019,13.022 -91.019,13.399 -91.472,13.852 -91.472,14.27 C17.1 -91.722,15.43 ; -88.948,18.448 -91.722,15.674 ; C6.1 -81.627,29.583 -80.943,29.583 U1.13@-80.39,29.03 ; P4.2 -76.3,12.67 -74.93,12.67 -73.441,11.181 -72.984,11.181 R11.1 ; BUZ1.1 -59.29,60.25 -15.66,60.25 -12.788,57.378 -12.788,44.9 R3.1 -12.788,21.346 ; R1.1@-36.408,43.57 R1.1 -31.6,43.52 -30.22,44.9 -12.81,44.9 ; R5.1@-36.392,19.753 -33.253,19.753 -31.66,21.346 -12.788,21.346 ; R7.1 -12.788,21.346 ; -12.78,21.346 -12.788,21.346 ; -91.965,15.674 -91.722,15.674 ; -91.965,15.674 -91.722,15.43 ; -91.722,15.43 -91.722,15.674
  Top Layer w0.5: P1.1 -91.59,25.31 -91.55,25.27 ; -88.66,18.25 -87.38,19.53 -87.38,25.14 -84.657,27.863 C2.1 C5.1 C6.1
  Top Layer w0.8: v1(-91.55,46.16) -91.55,25.27 -91.55,21.05 -88.948,18.448 -83.38,12.88 -80.51,12.88 P4.2
  Bottom Layer w0.5: v1(-91.55,46.16) -88.71,46.16 -78.44,56.43 BUZ1.1
VDD5: C12.1 C13.1 C14.1 C15.2 J1.A4-B9 J1.B4-A9 P3.1 P3.2 P3.3 P4.1 U2.3 | length 50.5
  Top Layer w0.65: J1.B4-A9 v2(-96.684,4.44) ; J1.A4-B9 v1(-96.684,9.24)
  Top Layer w0.8: P3.3 P3.2 P3.1 -98.39,13.63 -96.684,11.924 -96.684,10.102 v1(-96.684,9.24) v1@-96.684,9.23 ; -96.65,10.102 C12.1 C13.1 -82.348,10.102 -81.952,10.498 -81.012,10.498 P4.1 -79.63,9.46 -79.63,7.16 C14.1 -77.91,7.01 -74.46,3.56 -72.52,3.56 -71.9,4.18 -70.225,4.18 U2.3
  Bottom Layer w0.6: v2(-96.684,4.44) v1(-96.684,9.24)
pads on no net: H1.1 H2.1 H3.1 H4.1 H5.1 H6.1 J1.0 J1.A5 J1.A8 J1.B5 J1.B8 MARK1.1 P1.2 P1.3 P1.5 P1.11 P1.13 P1.17 P1.19 Q1. U1. U1.4 U1.48 U3. U3.4 U3.5 U3.6

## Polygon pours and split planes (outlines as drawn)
GND on Bottom Layer "GND_L02_P005" (solid, remove dead copper, pour order 5): -57.68,0.02 -57.68,19.06 -62.69,24.07 -71.74,24.07 -72.09,24.42 -72.09,27.18 -70.73,28.54 -62.53,28.54 -57.65,33.42 -57.65,43.75 -55.55,45.85 -0.21,45.85 0.04,46.1 0,46.14 0,62 -104.82,62 -104.97,61.85 -104.97,0 -58.01,0
GND on Bottom Layer "Bottom Layer-GND" (hatched 45Degree grid 2.286 track 0.178, remove dead copper, pour order 4): -64.24,23.83 -58.91,18.5 -58.91,0 0,0 0,46.51 -55.89,46.51 -58.24,44.16 -58.24,33.61 -62.73,29.12 -70.61,29.12 -72.43,27.3 -72.43,24.3 -71.96,23.83
GND on Top Layer "GND_L01_P007" (solid, remove dead copper, pour order 7): -57.68,0.02 -57.68,19.06 -62.69,24.07 -71.74,24.07 -72.09,24.42 -72.09,27.18 -70.73,28.54 -62.53,28.54 -57.65,33.42 -57.65,43.75 -55.55,45.85 -0.21,45.85 0.04,46.1 0,46.14 0,62 -104.82,62 -104.97,61.85 -104.97,0 -58.01,0

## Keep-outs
Keep-Out Layer:
  the board outline again, w0.2

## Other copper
Top Layer:
  pour cut-out: -94.11,8.78 -94.25,8.92 -94.25,9.56 -94.58,9.56 -94.52,9.5 -94.52,9.203
  region net GND: -98.118,3.64 -98.148,3.61 -98.8,3.61 -99.134,3.276 -99.232,3.276 -99.232,2.892 -98.93,2.59 -97.9,2.59 -97.43,3.06 -97.43,3.51 -97.6,3.68
  region net GND: -97.53,10 -97.53,10.99 -97.63,11.09 -98.603,11.09 -98.682,11.01 -98.682,10.192 -98.58,10.09
  pour cut-out: -79.456,48.04 -80.584,48.04 -80.71,47.914 -80.71,47.54 -79.74,47.54 -79.27,47.07
  pour cut-out: -64.276,14.12 -80.644,14.12 -80.644,14.626 -80.6,14.67 -64.36,14.67
  pour cut-out: -31.718,59.3 -30.482,59.3 -30.16,58.978 -30.16,58.48 -31.76,58.48
  pour cut-out: -34.258,47.44 -25.402,47.44 -25.402,48.142 -25.45,48.19 -25.53,48.11 -34.4,48.11
Bottom Layer:
  pour cut-out: -77.152,23.424 -77.297,23.278 -77.584,23.278 -77.584,23.397 -77.231,23.75 -77.09,23.75

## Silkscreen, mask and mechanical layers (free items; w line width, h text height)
Top Overlay:
  lines w0.2: -95.164,26.613 -93.211,26.613 ; -95.164,49.653 -90.736,49.653 ; -93.216,26.613 -90.736,26.613 ; -93.216,29.153 -90.766,29.153 ; -93.216,31.693 -90.766,31.693 ; -93.216,34.233 -90.766,34.233 ; -93.216,36.773 -90.766,36.773 ; -93.216,39.313 -90.766,39.313 ; -93.216,41.853 -90.766,41.853 ; -93.216,44.083 -90.766,44.083 ; -93.216,46.933 -90.766,46.933 ; -90.736,49.653 -93.211,49.653 -93.211,24.108 -90.736,24.108 -90.736,49.653
  lines w0.254: -33.969,34.783 ccw(c-39.968,34.67) -33.968,34.67 ; -33.965,10.514 ccw(c-39.964,10.401) -33.964,10.401 ; -10.395,34.804 ccw(c-16.394,34.691) -10.394,34.691 ; -10.325,10.464 ccw(c-16.324,10.351) -10.324,10.351
  text "NCC-P-NCCM0670-48LT-TOUCH_V01" at -65.44,59.47 h1.6
  text "YYWW" at -56.05,58.2 h1.6
  text "TX" at -76.6,56.191 h1.6 r90
  text "RX" at -73.83,55.955 h1.52 r90
  text "GND" at -71.17,55.15 h1.6 r90
  text "RST" at -89.328,54.62 h1.6 r90
  text "KEY" at -82.94,54.45 h1.6 r90
  text "PA4" at -70.57,43.525 h1.6 r90
  text "PA3" at -68.03,43.507 h1.6 r90
  text "PB7" at -62.95,43.513 h1.6 r90
  text "PC7" at -80.73,43.497 h1.6 r90
  text "PC9" at -75.65,43.504 h1.6 r90
  text "PC8" at -73.11,43.497 h1.6 r90
  text "PA0" at -65.49,43.504 h1.6 r90
  text "PC11" at -78.19,42.832 h1.6 r90
  text "RST" at -92.973,42.633 h1.4
  text "GND" at -93.908,36.76 h1.4 r90
  text "CLK" at -92.975,35.123 h1.4
  text "DIO" at -92.975,32.501 h1.4
  text "CH1" at -42.07,26.138 h2.5
  text "CH2" at -18.34,26.138 h2.5
  text "VDD" at -92.934,24.816 h1.4
  text "PC6" at -81.03,16.66 h1.6 r90
  text "PC5" at -78.49,16.66 h1.6 r90
  text "PC2" at -75.95,16.66 h1.6 r90
  text "PC1" at -73.41,16.66 h1.6 r90
  text "PC0" at -70.87,16.66 h1.6 r90
  text "PB15" at -68.33,16.66 h1.6 r90
  text "PB14" at -65.79,16.66 h1.6 r90
  text "PB13" at -63.25,16.66 h1.6 r90
  text "GND" at -104.24,16.37 h1.6
  text "5V" at -103.99,12.41 h1.6
  text "5V" at -81.72,12.37 h1.6
  text "VDD" at -79.46,12.24 h1.6
  text "3.3V" at -76.3,12.24 h1.6
  text "POW" at -66.85,10.751 h1.6
  text "GND" at -58.23,4.07 h1.6 r90
  text "OUT_3.3V" at -61.08,3.93 h1.6 r90
  text "CH3" at -42.12,1.848 h2.5
  text "CH4" at -18.39,1.848 h2.5
Mechanical 1:
  lines w0.1: -57,62 0,62 ; -57,0 0,0 0,61.98 -57,61.98 -57,0
  lines w0.2: -105,1.5 -105,0 -103.5,0 ; -105,60.5 -105,62 -103.5,62 ; -1.5,0 0,0 0,1.5 ; -1.5,62 0,62 0,60.5
  lines w0.254: -35.968,34.67 cw(c-39.968,34.67) -35.969,34.746 ; -35.964,10.401 cw(c-39.964,10.401) -35.965,10.477 ; -12.394,34.691 cw(c-16.394,34.691) -12.395,34.767 ; -12.324,10.351 cw(c-16.324,10.351) -12.325,10.427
